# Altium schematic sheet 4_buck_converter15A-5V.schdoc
size 528 x 134 mm; Symbol: Altium_Custom(2030*480); Device: Altium_Custom(2030*480); SheetNumber: 4; SheetTotal: 5; @Page No: 4; @Page Count: 5; @Schematic Name: Balance_batt_protection_SolidState_3; @Project Name: BFMC_Power Board V2; @Board Name: greater0603 Dsample; @Update Date: 2024-08-29; @Page Name: buck_converter15A-5V; @Create Time: 07:15:35; @Update Time: 10:15:39; @Create Date: 2024-08-29
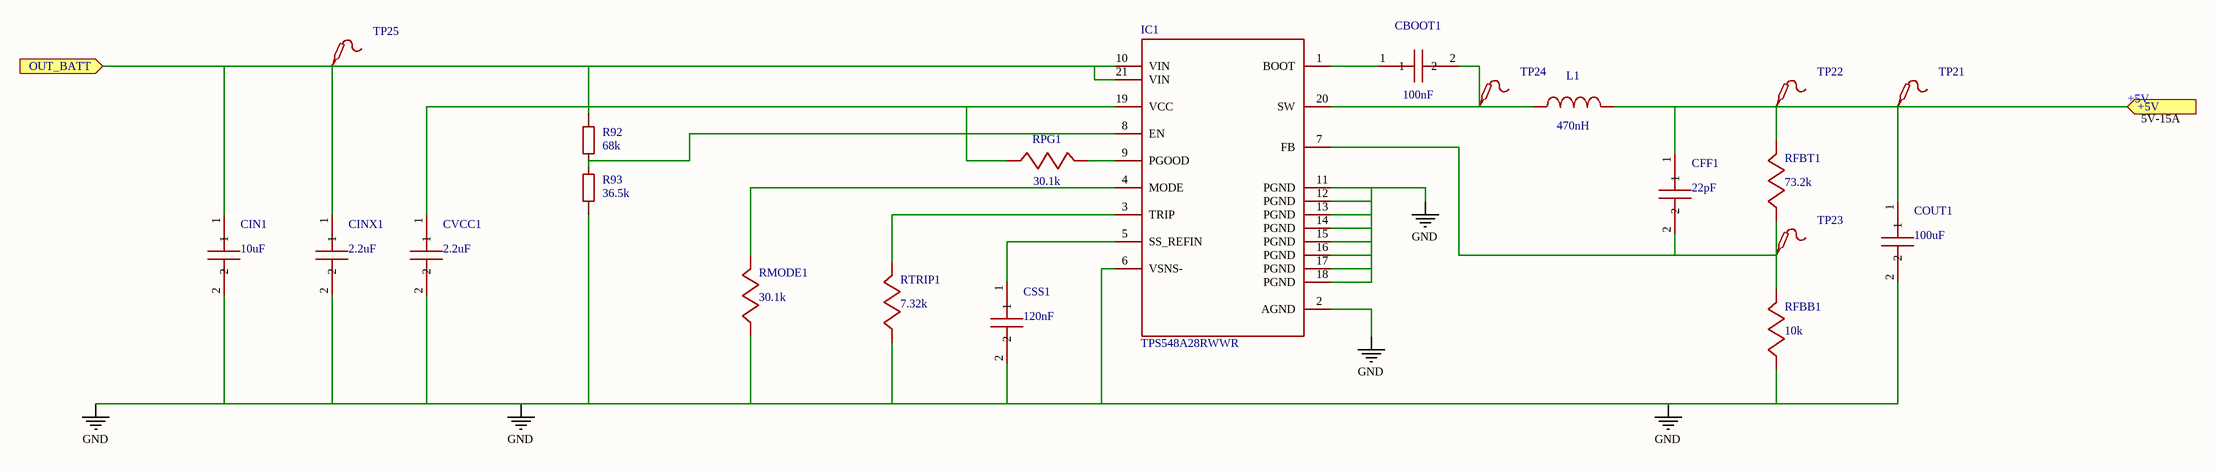
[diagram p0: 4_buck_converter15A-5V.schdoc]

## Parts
CBOOT1  value 100nF  [Cbst2]  (hidden comment: EMK105 B7104KVHF)
CFF1  C1005C0G1H220J: 22pF  [0603 0.5x0.8]  (hidden comment: C1005C0G1H220J)
CIN1  value 10uF  [Cin1 Aditome]  (hidden comment: GCJ31CC71E106K)
CINX1  value 2.2uF  [C0603]  (hidden comment: GCM188C71A225K)
COUT1  value 100uF  [C1210]  (hidden comment: EMK325ABJ107MM-T)
CSS1  value 120nF  [0603 0.5x0.8]  (hidden comment: C1608X7R1H154K)
CVCC1  value 2.2uF  [C0603]  (hidden comment: GCM188C71A225K)
IC1  TPS548A28RWWR  [TPS548B28RWWR]  (value not drawn)
L1  value 470nH  [IHLP4040DZERR47M11]  (hidden comment: IHLP4040DZERR47M11)
R92  68k  [R0603]  (value not drawn)
R93  36.5k  [R0603]  (value not drawn)
RFBB1  value 10k  [0805 dany2]  (hidden comment: SMM0204 50 10K 1 %)
RFBT1  value 73.2k  [0603 0.5x0.8]  (hidden comment: SMM0204 50 73K2 1 %)
RMODE1  value 30.1k  [1206R aditome]  (hidden comment: SMM0204 50 30K1 1 %)
RPG1  value 30.1k  [1206R aditome]  (hidden comment: SMM0204 50 30K1 1 %)
RTRIP1  value 7.32k  [Rtrip]  (hidden comment: SMM0204 50 7K32 1 %)
TP21  Test-Point  [Test-Point-0.5mm]  (value not drawn)
TP22  Test-Point  [Test-Point-0.5mm]  (value not drawn)
TP23  Test-Point  [Test-Point-0.5mm]  (value not drawn)
TP24  Test-Point  [Test-Point-0.5mm]  (value not drawn)
TP25  Test-Point  [Test-Point-0.5mm]  (value not drawn)

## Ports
+5V (in), OUT_BATT (in)

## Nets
GND: CIN1.2 CINX1.2 COUT1.2 CSS1.2 CVCC1.2 IC1.2(AGND) IC1.6(VSNS-) IC1.11(PGND) IC1.12(PGND) IC1.13(PGND) IC1.14(PGND) IC1.15(PGND) IC1.16(PGND) IC1.17(PGND) IC1.18(PGND) R93.1 RFBB1.2 RMODE1.2 RTRIP1.2
+5V: CFF1.1 COUT1.1 L1.1 RFBT1.1 TP21.1 TP22.1 ; port +5V
OUT_BATT: CIN1.1 CINX1.1 IC1.10(VIN) IC1.21(VIN) R92.2 TP25.1 ; port OUT_BATT
NetCBOOT1_1: CBOOT1.1 IC1.1(BOOT)
NetCBOOT1_2: CBOOT1.2 IC1.20(SW) L1.2 TP24.1
NetCFF1_2: CFF1.2 IC1.7(FB) RFBB1.1 RFBT1.2 TP23.1
NetCSS1_1: CSS1.1 IC1.5(SS_REFIN)
NetCVCC1_1: CVCC1.1 IC1.19(VCC) RPG1.2
NetIC1_3: IC1.3(TRIP) RTRIP1.1
NetIC1_4: IC1.4(MODE) RMODE1.1
NetIC1_8: IC1.8(EN) R92.1 R93.2
NetIC1_9: IC1.9(PGOOD) RPG1.1

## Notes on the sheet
- 5V-15A

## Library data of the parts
CBOOT1 = EMK105 B7104KVHF: EMK107B7104KA-T; Manufacturer Name: Taiyo Yuden; Symbol: Cboot; Add into BOM: yes; Origin Footprint: CAPC1005X55N
CFF1 = C1005C0G1H220J: C0402C240J3GACTU; Manufacturer Name: Kemet; Symbol: Cff; Add into BOM: yes; Origin Footprint: CAPC1005X55N
CIN1 = GCJ31CC71E106K: GRM31CR71E106KA1; Manufacturer Part Number: GRM31CR71E106KA12L; Manufacturer Name: MuRata; Symbol: Cin; Add into BOM: yes; Origin Footprint: CAPC3216X200N
CINX1 = GCM188C71A225K: C1608X7R1A225K08; Manufacturer Part Number: C1608X7R1A225K080AC; Manufacturer Name: TDK; Symbol: Cinx; Add into BOM: yes; Origin Footprint: CAPC1608X80N
COUT1 = EMK325ABJ107MM-T: CUSTOM1; Manufacturer Part Number: GENERIC_CAPACITOR; Manufacturer Name: CUSTOM; Symbol: Cout; Add into BOM: yes; Origin Footprint: CAPC3225X270N
CSS1 = C1608X7R1H154K: GRM155R61A124KE1; Manufacturer Part Number: GRM155R61A124KE19D; Manufacturer Name: MuRata; Symbol: Css; Add into BOM: yes; Origin Footprint: CAPC1005X55N
CVCC1 = GCM188C71A225K: GRM188R71A225KE1; Manufacturer Part Number: GRM188R71A225KE15D; Manufacturer Name: MuRata; Symbol: Cvcc; Add into BOM: yes; Origin Footprint: CAPC1608X80N
IC1 = TPS548A28RWWR: No Description Available; Manufacturer: Texas Instruments; Add into BOM: yes; Origin Footprint: RWW0021A
L1 = IHLP4040DZERR47M11: IHLP4040DZERR47M; Manufacturer Name: Vishay-Dale; Symbol: L1; Origin Footprint 2: INDPM108102X400N; Add into BOM: yes
R92 R93 = Res_0603: Symbol: Res; Convert to PCB: yes
RFBB1 = SMM0204 50 10K 1 %: CRCW040210K0FKED; Manufacturer Name: Vishay-Dale; Symbol: Rfbb; Add into BOM: yes; Origin Footprint: SMM02040D1501BB300
RFBT1 = SMM0204 50 73K2 1 %: CRCW040273K2FKED; Manufacturer Name: Vishay-Dale; Symbol: Rfbt; Add into BOM: yes; Origin Footprint: ERJ2RKD1004X
RMODE1 = SMM0204 50 30K1 1 %: CRCW040230K1FKED; Manufacturer Name: Vishay-Dale; Symbol: Rmode; Add into BOM: yes; Origin Footprint: SMM02040D1501BB300
RPG1 = SMM0204 50 30K1 1 %: CRCW040230K1FKED; Manufacturer Name: Vishay-Dale; Symbol: Rpg; Add into BOM: yes; Origin Footprint: SMM02040D1501BB300
RTRIP1 = SMM0204 50 7K32 1 %: Manufacturer Part Number: CRCW04027K32FKED; Manufacturer Name: Vishay-Dale; Add into BOM: yes; Origin Footprint: ERJ2RKD1004X
TP21-TP25 = Test-Point: Test Point 测试点; Add into BOM: yes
